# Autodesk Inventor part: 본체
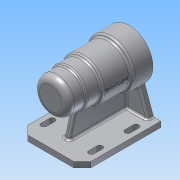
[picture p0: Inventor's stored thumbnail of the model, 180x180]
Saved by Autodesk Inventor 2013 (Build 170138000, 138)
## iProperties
Created: 2017-09
Part Number: 본체
Material: 알루미늄 6061
Document SubType Name: Modeling
Designer: user
Density: 1 g/cm^3
Author: user
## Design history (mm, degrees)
sketch "스케치1"
  geometry: L1 (0, 0)-(0, 34); L2 (0, 0)-(-112, 0); L3 (-112, 0)-(-112, 25); L4 (-112, 25)-(-87, 25); L5 (-87, 25)-(-87, 27); L6 (-87, 27)-(-67, 27); L7 (-67, 27)-(-67, 30); L8 (-67, 30)-(-28, 30); L9 (-28, 30)-(-28, 34); L10 (-28, 34)-(0, 34)
  constraints: 20 end point, 5 perpendicular, 3 parallel, 1 horizontal, 1 vertical
  dimensions: "d0" = 34 distance of L1.start L1.end; "d1" = 112 distance of L1.start L2.end; "d2" = 25 distance of L2.end L3.end; "d3" = 25 distance of L3.end L4.end; "d4" = 2 distance of L4.end L5.end; "d5" = 20 distance of L5.end L6.end; "d6" = 3 distance of L6.end L7.end; "d7" = 39 distance of L7.end L8.end
revolve "회전1" sketch "스케치1" stored, may be unused: angle "d8" = 90 deg
sketch "스케치2"
  geometry: L1 (-112, -25)-(-112, 25) reference; L2 (-112, 25)-(-87, 25) reference; L3 (-87, 25)-(-87, 27) reference; L4 (-87, 27)-(-67, 27) reference; L5 (-67, 27)-(-67, 30) reference; L6 (-67, 30)-(-28, 30) reference; L7 (-28, 30)-(-28, 34) reference; L8 (-28, 34)-(0, 34) reference; L9 (0, 34)-(0, -34) reference; L10 (0, -34)-(-28, -34) reference; L11 (-28, -34)-(-28, -30) reference; L12 (-28, -30)-(-67, -30) reference; L13 (-67, -30)-(-67, -27) reference; L14 (-67, -27)-(-87, -27) reference; L15 (-87, -27)-(-87, -25) reference; L16 (-87, -25)-(-112, -25) reference; L17 (-112, 0)-(0, 0); L18 (0, 0)-(0, 21); L19 (0, 21)-(-15, 21); L20 (-15, 21)-(-15, 21); L21 (-18, 24)-(-66, 24); L22 (-69, 21)-(-69, 21); L23 (-69, 21)-(-80.7, 21); L24 (-81, 20.7)-(-81, 17.5); L25 (-81, 17.5)-(-98.7, 17.5); L26 (-99, 17.2)-(-99, 16); L27 (-99, 16)-(-102.7, 16); L28 (-103, 15.7)-(-103, 10.5); L29 (-103, 10.5)-(-104, 10.5); L30 (-106, 8.5)-(-106, 0); L31 (-106, 0)-(0, 0); A1 r 2 centre (-104, 8.5) between (-104, 10.5) and (-106, 8.5); A2 r 3 centre (-66, 21) between (-66, 24) and (-69, 21); A3 r 3 centre (-18, 21) between (-15, 21) and (-18, 24); A4 r 0.3 centre (-102.7, 15.7) between (-102.7, 16) and (-103, 15.7); A5 r 0.3 centre (-98.7, 17.2) between (-98.7, 17.5) and (-99, 17.2); A6 r 0.3 centre (-80.7, 20.7) between (-80.7, 21) and (-81, 20.7); 6 further points
  constraints: 30 end point, 14 point on line, 12 point on circle, 12 tangent, 7 parallel, 6 centre point, 6 perpendicular, 3 equal radius, 1 collinear, 1 midpoint
  dimensions: "d9" = 21 distance of L17.end L18.end; "d10" = 15 distance of L18.end L19.end; "d11" = 3 distance of L19.end point (-15, 24); "d12" = 54 distance of point (-15, 24) point (-69, 24); "d13" = 3 distance of point (-69, 24) L22.end; "d14" = 12 distance of L22.end point (-81, 21); "d15" = 3.5 distance of point (-81, 21) L24.end; "d16" = 18 distance of L24.end point (-99, 17.5); "d17" = 1.5 distance of point (-99, 17.5) L26.end; "d18" = 4 distance of L26.end point (-103, 16); "d19" = 5.5 distance of point (-103, 16) L28.end; "d20" = 3 distance of L28.end point (-106, 10.5); "d21" = 2 radius of A1; "d22" = 3 radius of A2; "d23" = 0.3 radius of A4
revolve "회전2" sketch "스케치2" stored, may be unused: angle "d24" = 90 deg
fillet "모깎기1" dims "d25" = 9
fillet "모깎기2" dims "d26" = 3
chamfer "모따기1" distance "d27" = 1; stored, may be unused: second distance "d28" = 2, angle "d29" = 45 deg
node "작업 평면1"
sketch "스케치3"
  geometry: L1 (100, -45)-(0, -45); L2 (0, -45)-(0, 45); L3 (0, 45)-(100, 45); L4 (112, 33)-(112, -33); L5 (112, -33)-(100, -45); L6 (100, 45)-(112, 33); 4 further points
  constraints: 12 end point, 4 point on line, 2 midpoint, 2 parallel, 1 coincident, 1 horizontal, 1 perpendicular
  dimensions: "d31" = 112 distance of point (112, -45) L1.end; "d33" = 90 distance of L1.end L2.end; "d34" = 12 distance of L4.end point (112, -45); "d35" = 12 distance of L1.start point (112, -45) (= d34); "d36" = 12 distance of L3.end point (112, 45) (= d34); "d37" = 12 distance of L4.start point (112, 45) (= d36)
extrude "돌출1" join sketch "스케치3" distance "d38" = 8; taper "d39" = 0 deg
sketch "스케치4"
  geometry: L1 (0, -45)-(0, 45) reference; L2 (-112, 33)-(-112, -33) reference; L3 (-90, 4)-(0, 4); L4 (0, 4)-(0, -4); L5 (0, -4)-(-90, -4); L6 (-90, -4)-(-90, 4); 3 further points
  constraints: 8 end point, 2 midpoint, 2 parallel, 1 horizontal, 1 horizontal alignment, 1 perpendicular, 1 point on line
  dimensions: "d40" = 8 distance of L5.end L3.start; "d42" = 22 distance between parallel lines of L2 L6
extrude "돌출2" join sketch "스케치4" stored distance "d43" = 8; taper "d44" = 0 deg
feature "면 기울기1" dims angle "d45" = 15 deg
sketch "스케치5"
  geometry: L1 (0, 8)-(41, 8) reference; L2 (0, 0)-(0, 8) reference; L3 (10, 8)-(23.1, 43.992); A1 r 34 centre (45, 70) between (49, 36.236) and (41, 36.236) reference
  constraints: 2 end point, 1 point on circle, 1 point on line
  dimensions: "d46" = 110 deg angle of L1 L3; "d47" = 10 distance from line of L2 L3.start
feature "리브1" sketch "스케치5" dims "d48" = 1, "d49" = 8, "d50" = 0, "d51" = 0, "d52" = 1, "d53" = 1
sketch "스케치6"
  geometry: L1 (-90, -4)-(-90, 4) reference; L2 (0, 35)-(0, 45) reference; L3 (-112, 33)-(-112, -33) reference; L4 (-88, 38)-(-76, 38); L5 (-88, 30)-(-76, 30); L6 (-36, 38)-(-24, 38); L7 (-36, 30)-(-24, 30); L8 (-90, 0)-(0, 0); L9 (-36, -30)-(-24, -30); L10 (-36, -38)-(-24, -38); L11 (-88, -30)-(-76, -30); L12 (-88, -38)-(-76, -38); A1 r 4 centre (-88, 34) between (-88, 38) and (-88, 30); A2 r 4 centre (-76, 34) between (-76, 30) and (-76, 38); A3 r 4 centre (-24, 34) between (-24, 30) and (-24, 38); A4 r 4 centre (-36, 34) between (-36, 38) and (-36, 30); A5 r 4 centre (-24, -34) between (-24, -38) and (-24, -30); A6 r 4 centre (-36, -34) between (-36, -30) and (-36, -38); A7 r 4 centre (-76, -34) between (-76, -38) and (-76, -30); A8 r 4 centre (-88, -34) between (-88, -30) and (-88, -38)
  constraints: 18 end point, 16 point on circle, 12 symmetric about line, 8 centre point, 5 vertical alignment, 4 tangent, 2 parallel, 1 midpoint, 1 perpendicular, 4 other
  dimensions: "d54" = 8 diameter of A1; "d55" = 12 distance of L4.start L4.end; "d56" = 12 distance of L5.start L5.end; "d57" = 34 vertical distance of L8.end A1.centre; "d58" = 8 diameter of A4; "d59" = 12 distance of L6.start L6.end; "d60" = 12 distance of L7.start L7.end; "d61" = 40 distance of A4.centre A2.centre; "d62" = 24 distance from line of L2 A3.centre; "d63" = 34 vertical distance of L8.end A3.centre
extrude "돌출3" cut sketch "스케치6" stored distance "d64" = 8; taper "d65" = 0 deg
node "작업 평면2"
sketch "스케치7"
  geometry: L1 (-17.092, 2.402)-(16.092, 2.402); L2 (16.092, 2.402)-(16.092, -2.402); L3 (16.092, -2.402)-(-17.092, -2.402); L4 (-17.092, -2.402)-(-17.092, 2.402); L5 (-17.092, -2.402)-(16.092, 2.402); L6 (47.5, -26.008)-(47.5, 34) reference; 3 further points
  constraints: 2 end point, 2 midpoint, 1 horizontal, 1 horizontal alignment, 2 other
  dimensions: "d66" = 4.80326 distance of L3.end L1.start; "d68" = 33.18318 distance of L1.start L1.end; "d69" = 48 distance from line of L6 point (-0.5, 0)
feature "엠보싱1" sketch "스케치7" dims "d0" = 34, "d1" = 112, "d2" = 25, "d3" = 25, "d4" = 2, "d5" = 20, "d6" = 3, "d7" = 39, "d9" = 21, "d10" = 15, "d11" = 3, "d12" = 54, "d13" = 3, "d14" = 12, "d15" = 3.5, "d16" = 18, "d17" = 1.5, "d18" = 4, "d19" = 5.5, "d20" = 3, "d21" = 2, "d22" = 3, "d23" = 0.3, "d70" = 0.5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
sketch "스케치8" dims "d72" = 52
  geometry: C1 r 22 at (45, 70) reference; A1 r 34 centre (45, 70) between (66.9, 43.992) and (23.1, 43.992) reference; 2 further points
  constraints: 2 vertical alignment, 1 coincident, 2 other
hole "구멍1" sketch "스케치8" at (45, 96) diameter "d73" = 3.242; stored, may be unused: countersink angle "d77" = 90 deg, drill point angle "d79" = 118 deg; dims "d74" = 8, "d75" = 4, "d76" = 2, "d78" = 11
fillet "모깎기3" dims "d83" = 3
fillet "모깎기4" dims "d84" = 3
fillet "모깎기5" dims "d85" = 3
node "솔리드1"
mirror "대칭1"
pattern_circular "원형 패턴1" dims angle "d81" = 360 deg
node "절단 모서리 투영1"
